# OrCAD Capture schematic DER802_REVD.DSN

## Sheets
1 PAGE1: size C; title: DER 802; rev: D
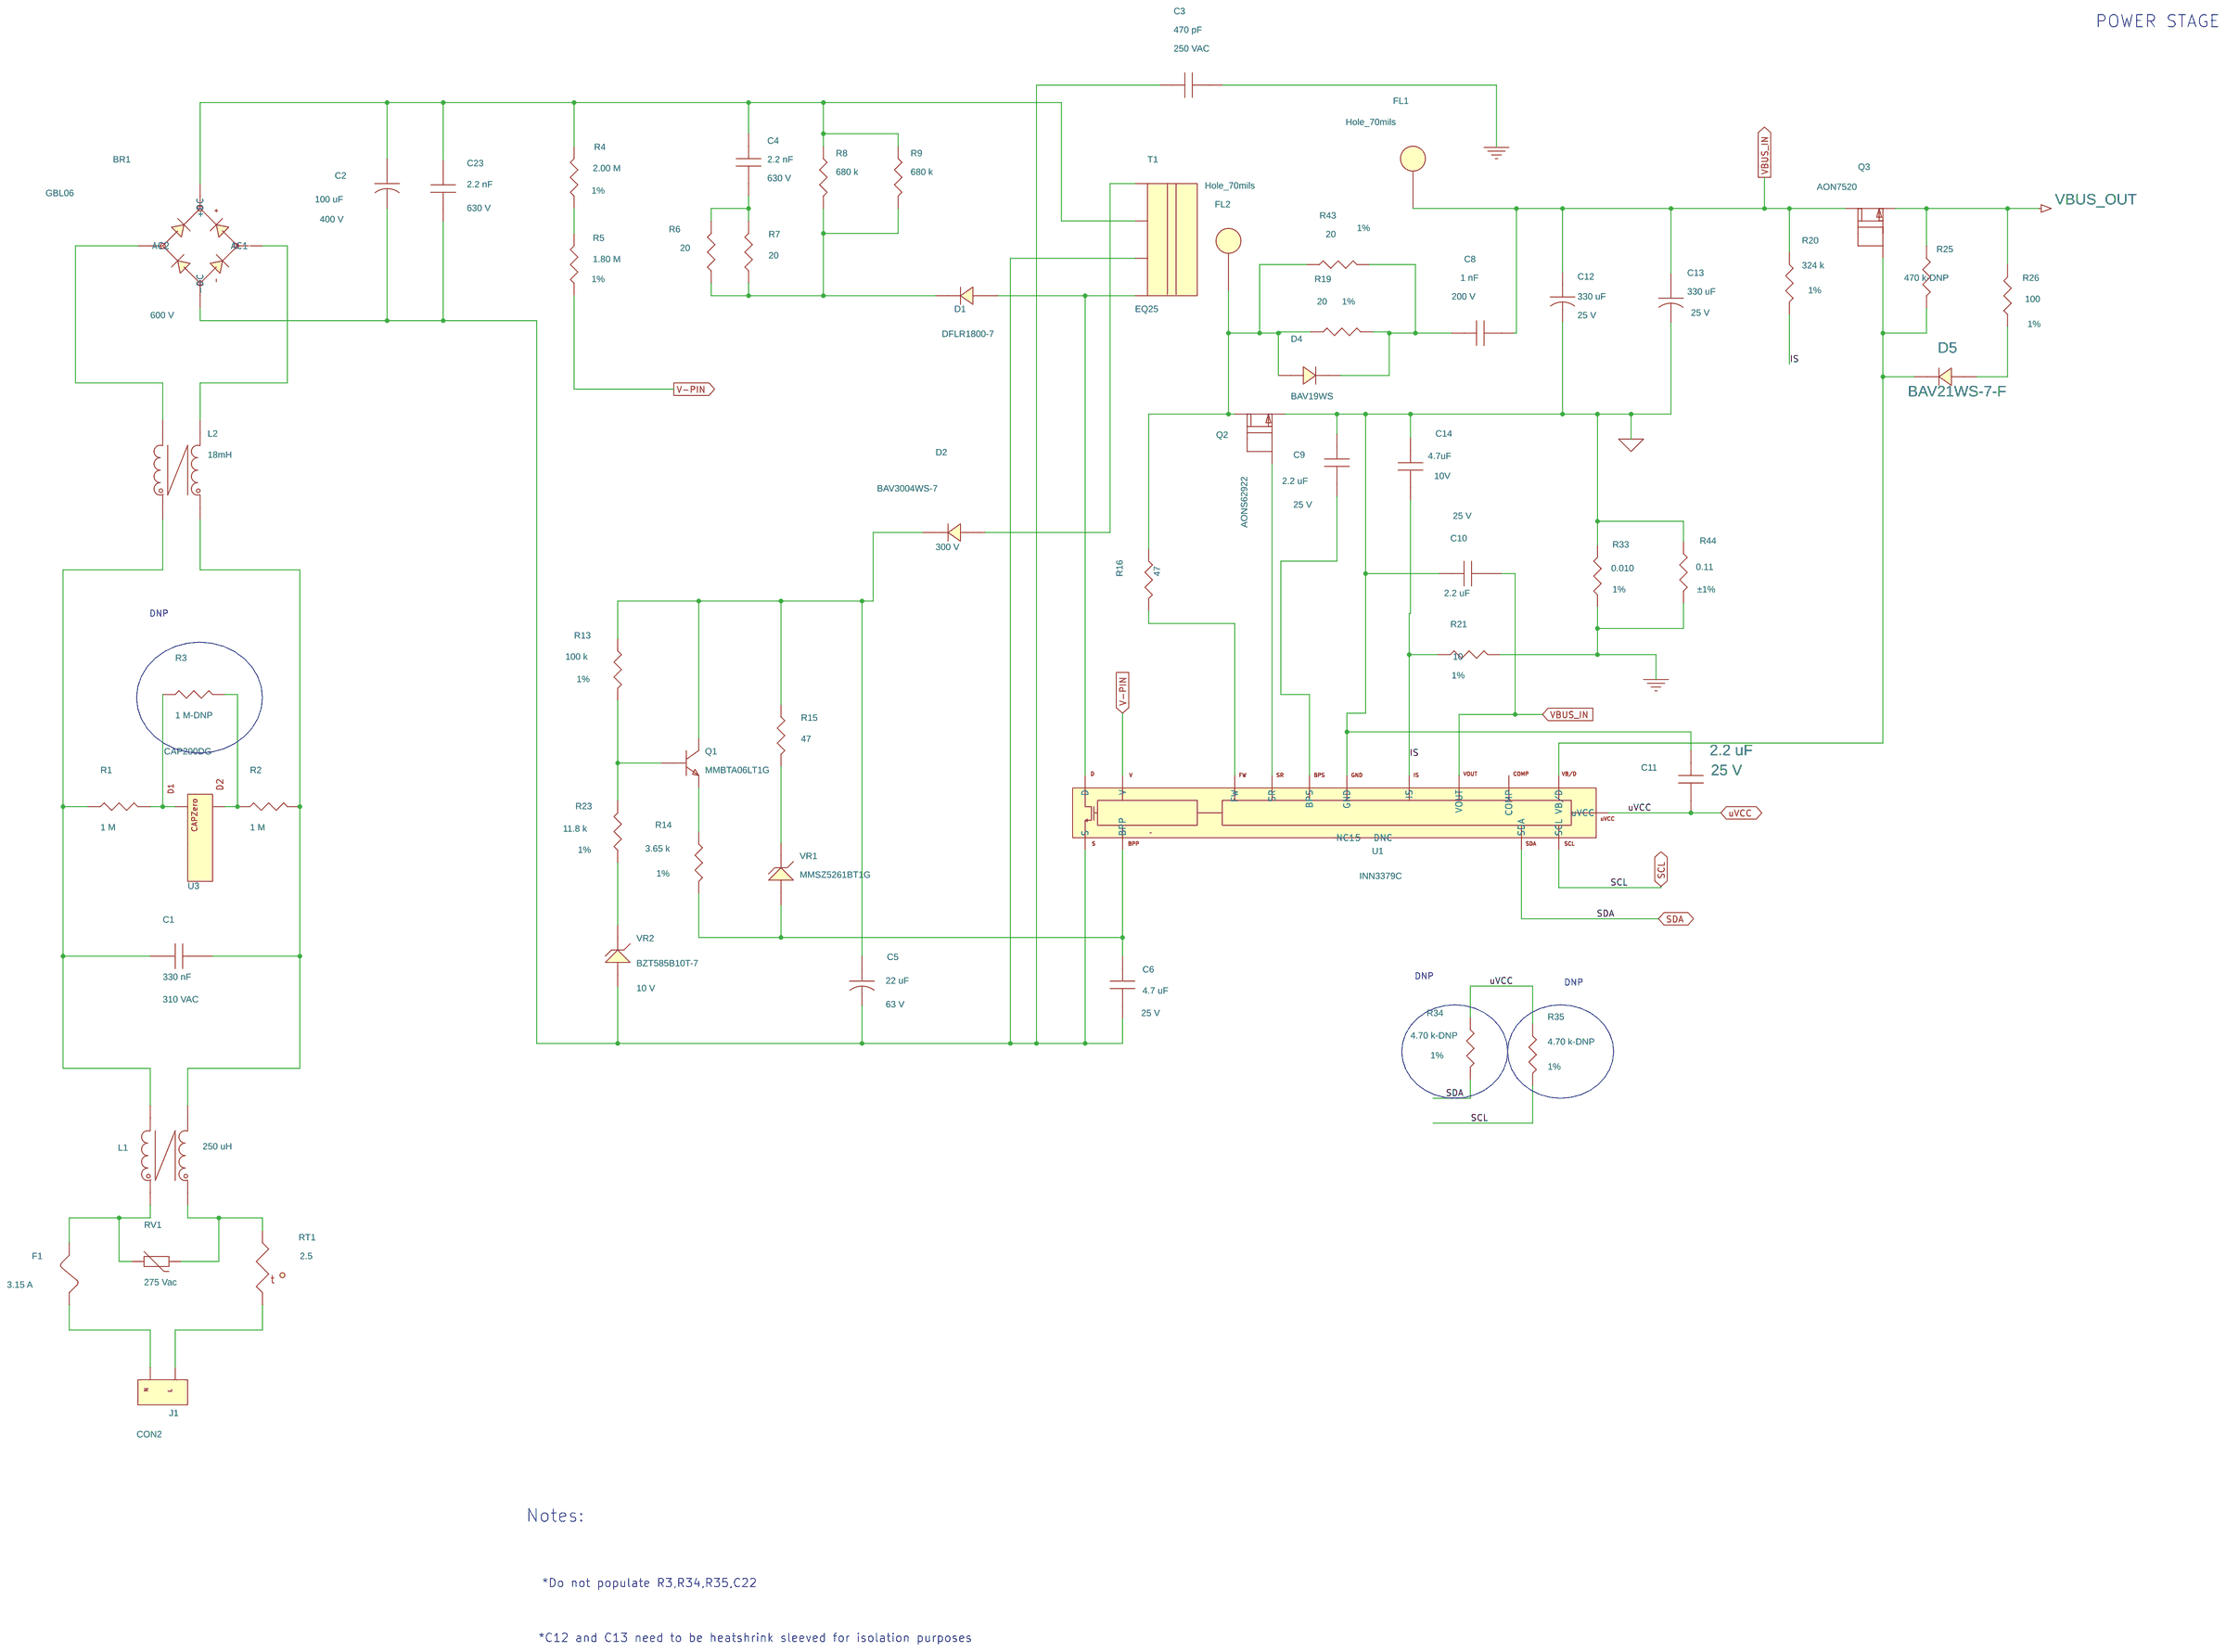
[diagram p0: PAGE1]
2 PAGE2: size Custom; rev: A
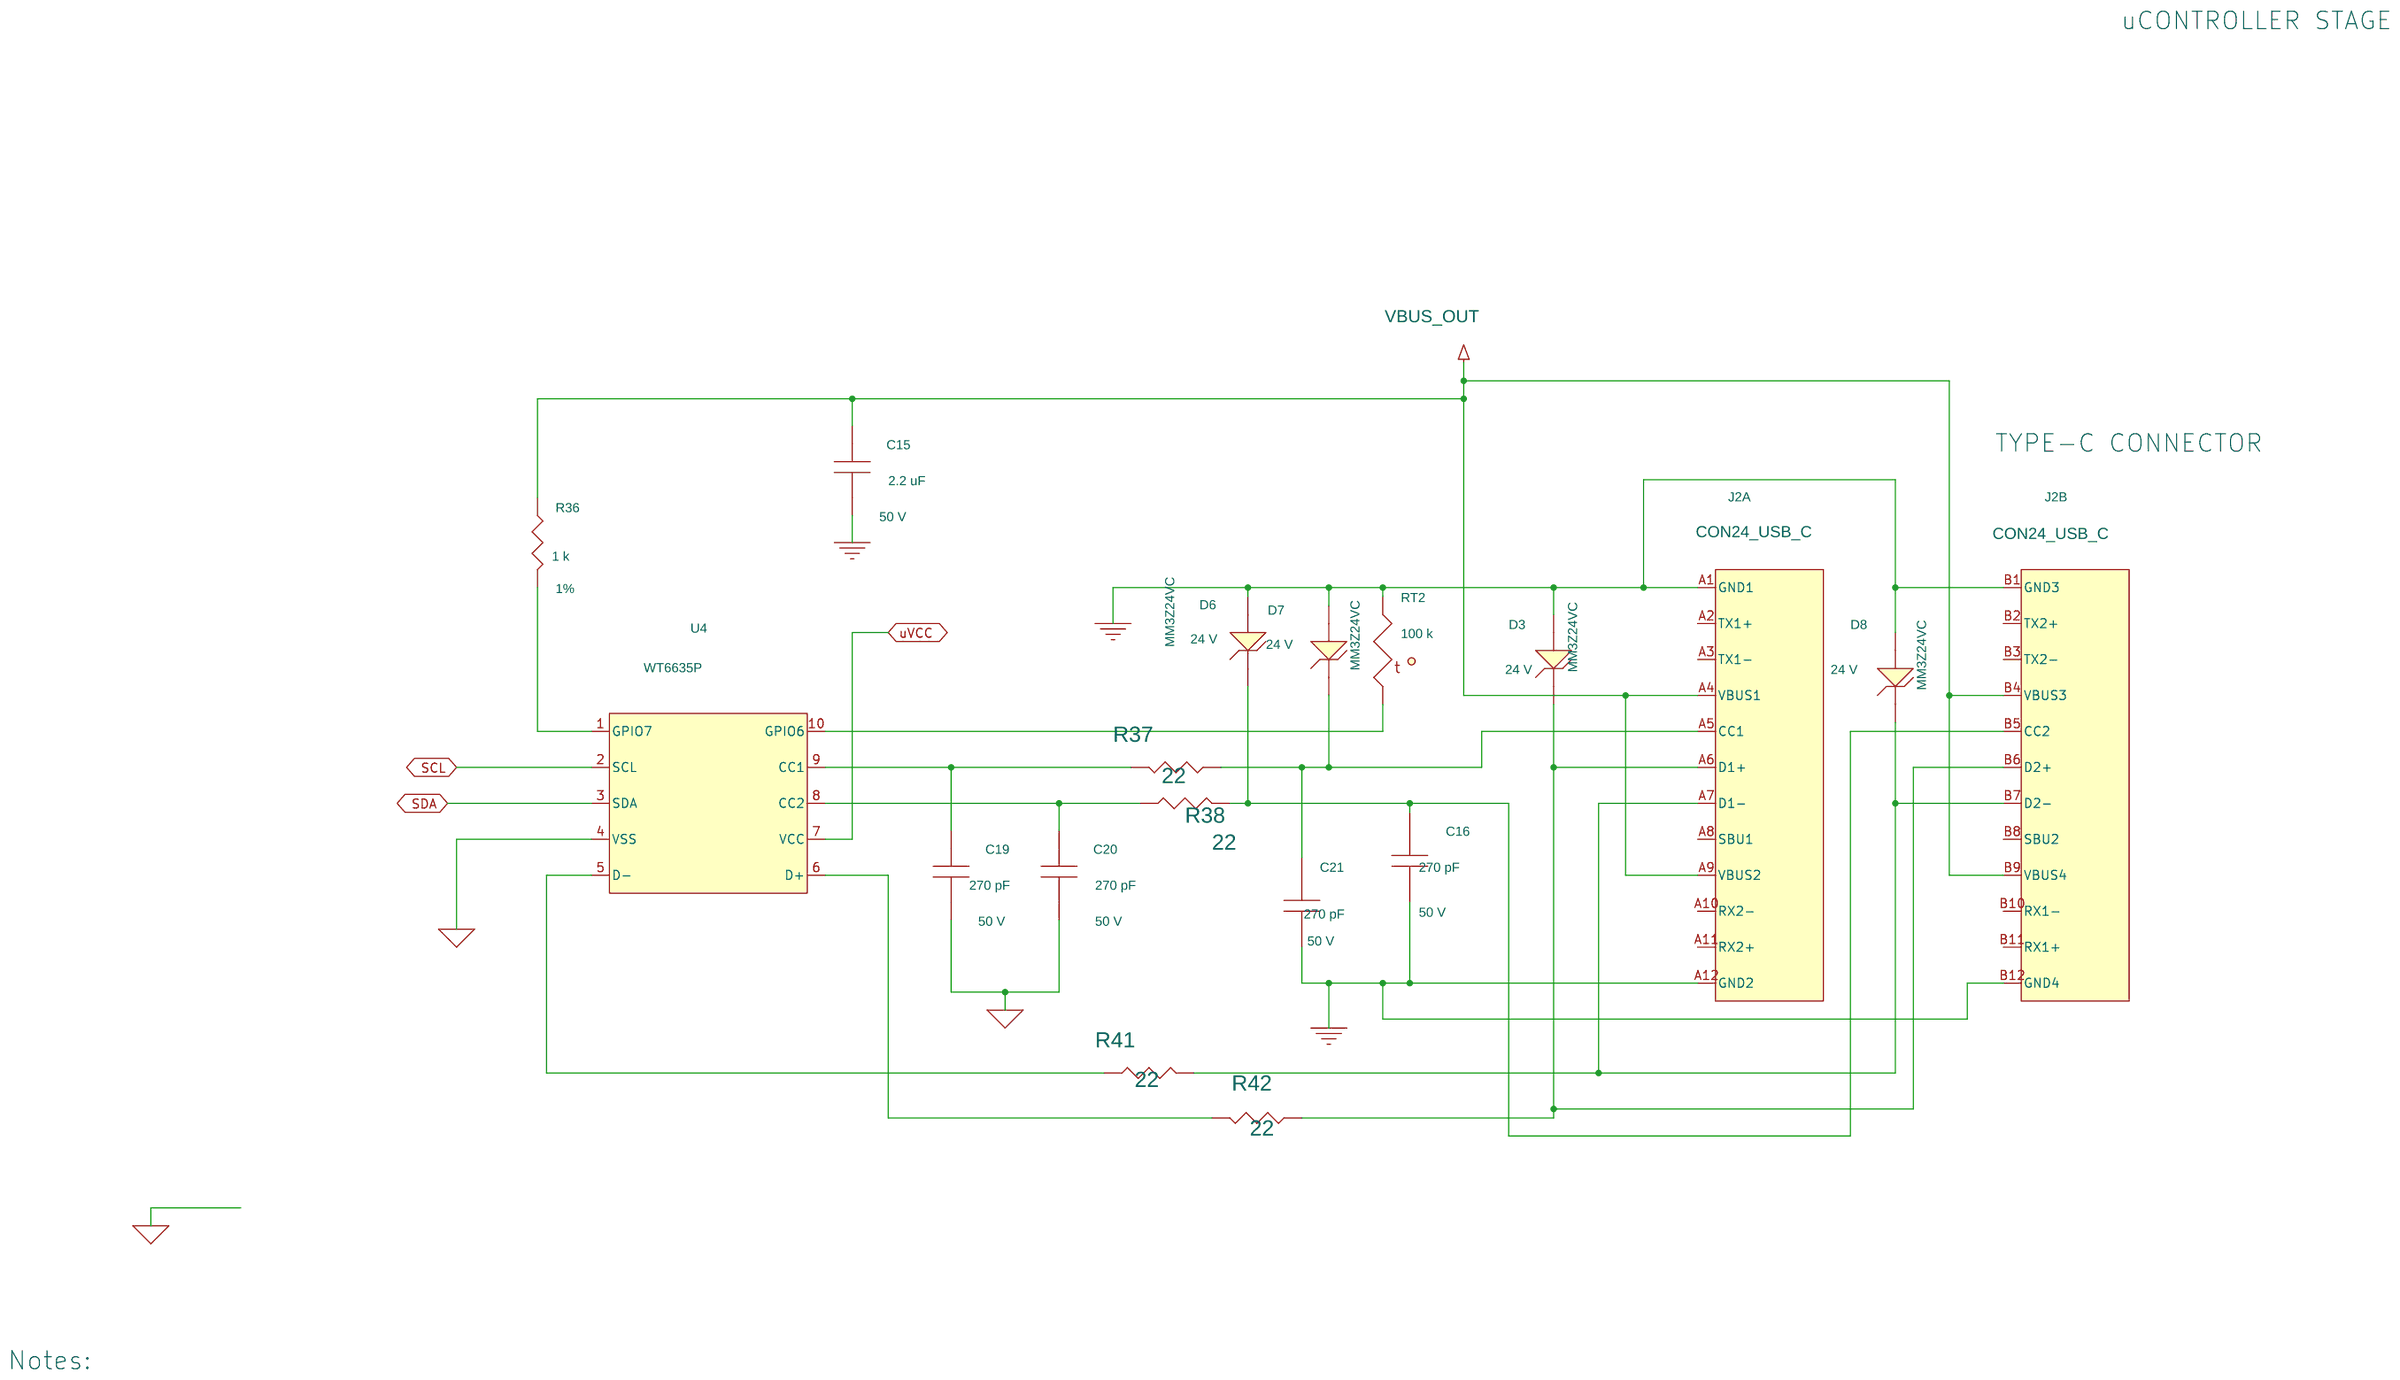
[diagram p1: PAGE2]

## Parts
sheet PAGE1
BR1  GBL06  [pidaxbridgegbl06]
C1  330 nF  [pinpxcaprad710x315590046]
C2  100 uF  [pipolcapclyd630ls300040]
C3  470 pF  [pinpcaprad374x275ls394d040]
C4  2.2 nF  [pismc1206]
C5  22 uF  [pipolcapclyd200ls80030]
C6  4.7 uF  [pismc0805]
C8  1 nF  [pismc0805]
C9  2.2 uF  [pismc0805]
C10  2.2 uF  [pismc0805]
C11  2.2 uF  [pismc0805]
C12  330 uF  [pipolcapcyld315ls138d030]
C13  330 uF  [pipolcapcyld315ls138d030]
C14  4.7uF  [pismc0603]
C23  2.2 nF  [pismc1206]
D1  DFLR1800-7  [pismddflr120012]
D2  BAV3004WS-7  [pismsod323]
D4  BAV19WS  [pismsod323]
D5  BAV21WS-7-F  [pismsod323]
F1  3.15 A  [pi_rst_microfuse]
FL1  Hole_70mils  [pi_hole_70mil]
FL2  Hole_70mils  [pi_hole_70mil]
J1  CON2  [PI_IEC320-C8]
L1  250 uH  [pi_toroid_CMC4p_V_275uH]
L2  18mH  [pi_CMC_18mH_Sumida]
Q1  MMBTA06LT1G  [pismsot23123_1]
Q2  AONS62922  [pismpqfn5x6b]
Q3  AON7520  [pism8dfn_ep3p3x3p3a]
R1  1 M  [pismr1206]
R2  1 M  [pismr1206]
R3  1 M-DNP  [pismr1206]
R4  2.00 M  [pismr1206]
R5  1.80 M  [pismr1206]
R6  20  [pismr1206]
R7  20  [pismr1206]
R8  680 k  [pismr1206]
R9  680 k  [pismr1206]
R13  100 k  [pismr0603]
R14  3.65 k  [pismr0603]
R15  47  [pismr0603]
R16  47  [pismr0603]
R19  20  [pismr1206]
R20  324 k  [pismr0805]
R21  10  [pismr0603]
R23  11.8 k  [pismr0805]
R25  470 k-DNP  [pismr0603]
R26  100  [pismr0603]
R33  0.010  [pismr0805]
R34  4.70 k-DNP  [pismr0402]
R35  4.70 k-DNP  [pismr0402]
R43  20  [pismr1206]
R44  0.11  [pismr0805]
RT1  2.5  [pi_rad150x300ls200d030]
RV1  275 Vac  [pidisc350x160ls210x140040]
T1  EQ25  [pi_bobbin_eq-2515p5_4p]
U1  INN3379C  [pi_ic_insop_24d]
U3  CAP200DG  [pi_ic_smd_so8_capzero]
VR1  MMSZ5261BT1G  [pi_sm_sod-123_12]
VR2  BZT585B10T-7  [pi_sm_d_ssmini2p]
sheet PAGE2
C15  2.2 uF  [pismc1206]
C16  270 pF  [pismc0603]
C19  270 pF  [pismc0603]
C20  270 pF  [pismc0603]
C21  270 pF  [pismc0603]
D3  MM3Z24VC  [pismsod323F]
D6  MM3Z24VC  [pismsod323F]
D7  MM3Z24VC  [pismsod323F]
D8  MM3Z24VC  [pismsod323F]
J2  CON24_USB_C  [pi_conn_USBC_Wurth]  (sections A,B)
R36  1 k  [pismr0603]
R37  22  [pismr0603]
R38  22  [pismr0603]
R41  22  [pismr0603]
R42  22  [pismr0603]
RT2  100 k  [pismr0603]
U4  WT6635P  [pismsop10]

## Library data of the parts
BR1 = DISCRETE_BRIDGE_+~~-: Disp_Voltage: 600 V; Part Number: 15-01112-00
C1 = CAP_NP: Disp_Voltage: 310 VAC; Part Number: 20-08604-00; Voltage: 310 VAC
C2 = CAP_POL: ALT_SYMBOLS: pipolcapclyd630ls3000401120h; COMPGROUP: 1; Disp_Voltage: 400 V; FPLIST: pipolcapclyd630ls300040,pipolcapclyd630ls3000401120h; Part Number: 20-00517-00; Voltage: 400 V
C3 = CAP_NP: COMPGROUP: 3; Disp_Voltage: 250 VAC; PCB Editor PCBFP: pinpycaprad540x290ls400040; Part Number: 20-09075-00; Voltage: 250 VAC
C4 = CAP_NP_0: Disp_Voltage: 630 V; Part Number: 20-08609-00; Voltage: 630 V
C5 = CAP_POL: ALT_SYMBOLS: pipolcapclyd5p0x12p5ls2p0d30h; Disp_Voltage: 63 V; FPLIST: pipolcapclyd200ls80030,pipolcapclyd5p0x12p5ls2p0d30h; Part Number: 20-09168-00; Voltage: 63 V
C6 = CAP_NP: Disp_Voltage: 25 V; Part Number: 20-09022-00; Voltage: 25 V
C8 = CAP_NP: ALT_SYMBOLS: pismc0805_1; Disp_Voltage: 200 V; FPLIST: pismc0805,pismc0805_1; PCB Editor PCBFP: pismc0603; Part Number: 20-00737-00; Voltage: 200 V
C9 = CAP_NP_0: Disp_Voltage: 25 V; Part Number: 20-08603-00; Voltage: 25 V
C10 C11 = CAP_NP: Disp_Voltage: 25 V; Part Number: 20-08603-00; Voltage: 25 V
C12 C13 = CAP_POL: ALT_SYMBOLS: pipolcapcyld315ls138d030h; Disp_Voltage: 25 V; FPLIST: pipolcapcyld315ls138d030,pipolcapcyld315ls138d030h; Part Number: 20-09107-00; Voltage: 25 V
C14 = CAP_NP: Disp_Voltage: 10V; Part Number: 20-08591-00; Voltage: 10 V
C23 = CAP_NP: Disp_Voltage: 630 V; Part Number: 20-08609-00; Voltage: 630 V
D1 = DIODE: COMPGROUP: 2; Part Number: 15-00919-00
D2 = DIODE: COMPGROUP: 1; Disp_Voltage: 300 V; Part Number: 15-01138-00
D4 = DIODE: Part Number: 15-00658-00
D5 = DIODE: COMPGROUP: 1; Part Number: 15-00385-00
F1 = FUSE: ALT_SYMBOLS: pirstmicrofusehoz; COMPGROUP: 1; FPLIST: pi_rst_microfuse,pirstmicrofusehoz; Part Number: 40-00020-00
FL1 FL2 = FlyingLead: Part Number: 35-00282-00
J1 = CON2_ACIN: Part Number: 35-00360-00
L1 = TORRID_4P_12_34: ALT_SYMBOLS: pi_toroid_CMC4p_V,pi_toroid_CMC4p_V_275uH; FPLIST: pi_toroid_CMC4p_H,pi_toroid_CMC4p_V,pi_toroid_CMC4p_V_275uH; Part Number: 32-00367-00
L2 = TORRID_4P_12_43a: Part Number: 30-00462-00
Q1 = NPN_BEC: Part Number: 55-00072-00
Q2 = FET_N_SGD_123_4_5678: Part Number: 50-00275-00
Q3 = FET_N_SGD_123_4_5678: Part Number: 50-00300-00
R1-R3 = R: Part Number: 05-01424-00
R4 = R: Disp_Tol: 1%; Part Number: 05-03156-00
R5 = R: Disp_Tol: 1%; Part Number: 05-03155-00
R6 R7 = R: Part Number: 05-01311-00
R8 R9 = R: Part Number: 05-01420-00
R13 = R: Disp_Tol: 1%; Part Number: 05-01174-00
R14 = R: Disp_Tol: 1%; Part Number: 05-01132-00
R15 R16 = R: Part Number: 05-01656-00
R19 R43 = R: Disp_Tol: 1%; Part Number: 05-00030-00
R20 = R: Disp_Tol: 1%; Part Number: 05-00829-00
R21 = R: Disp_Tol: 1%; Part Number: 05-00886-00
R23 = R: Disp_Tol: 1%; Part Number: 05-00691-00
R25 = R: Part Number: 05-01752-00
R26 = R: Disp_Tol: 1%; Part Number: 05-00982-00
R33 = R: Disp_Tol: 1%; Part Number: 05-06574-00
R34 R35 = R: ALT_SYMBOLS: RC0402; Disp_Tol: 1%; FPLIST: pismr0402,RC0402; Part Number: 05-05899-00
R44 = R: Disp_Tol: ±1%; Part Number: 05-06526-00
RT1 = THERMISTOR: ALT_SYMBOLS: pirad400x300ls200040_h; FPLIST: pi_rad150x300ls200d030,pirad400x300ls200040_h; Part Number: 90-00040-00
RV1 = VARISTOR: ALT_SYMBOLS: pi_disc_354x220_ls220x10_040_h; FPLIST: pidisc350x160ls210x140040,pi_disc_354x220_ls220x10_040_h; Part Number: 85-00015-00
T1 = BEQ2506_4P: Part Number: 25-01141-00
U1 = DEV_InnoPro: Part Number: 10-01092-00
U3 = CAPZero: Part Number: 10-00958-00
VR1 = DIODE_ZENER: Part Number: 15-01102-00
VR2 = DIODE_ZENER: Disp_Voltage: 10 V; Part Number: 15-01640-00
C15 = CAP_NP: Disp_Voltage: 50 V; Part Number: 20-09241-00; Voltage: 50 V
C16 C19-C21 = CAP_NP: Disp_Voltage: 50 V; Part Number: 20-09122-00; Voltage: 50 V
D3 D6-D8 = DIODE_ZENER: Disp_Voltage: 24 V; Part Number: 15-01590-00
J2 = CON24_USB: Part Number: 35-00414-00
R36 = R: Disp_Tol: 1%; Part Number: 05-01078-00
R37 R38 R41 R42 = R: COMPGROUP: 1; Part Number: 05-01648-00
RT2 = THERMISTOR: Part Number: 90-00078-00
U4 = WT6635P-10: Part Number: 45-00487-00

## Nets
GND: C3.2 C15.2 C16.1 C21.1 D3.2 D6.2 D7.2 D8.2 J2.A1(GND1) J2.A12(GND2) J2.B1(GND3) J2.B12(GND4) R21.2 R33.1 R44.2 RT2.1
GND_SIGNAL: C9.1 C10.1 C11.1 C12.2 C13.2 C14.1 C19.2 C20.2 Q2.1(S) R33.2 R44.1 U1.2(GND) U4.4(VSS)
VBUS_IN: C8.2 C10.2 C12.1 C13.1 FL1.1 Q3.5(D) R20.1 U1.10(VOUT)
VBUS_OUT: C15.1 J2.A4(VBUS1) J2.A9(VBUS2) J2.B4(VBUS3) J2.B9(VBUS4) Q3.1(S) R25.1 R26.2 R36.2
IS: C14.2 R20.2 R21.1 U1.1(IS)
SCL: R35.2 U1.5(SCL) U4.2(SCL)
SDA: R34.2 U1.6(SDA) U4.3(SDA)
uVCC: C11.2 R34.1 R35.1 U1.7(uVCC) U4.7(VCC)
V-PIN: R5.1 U1.13(V)
N10479111: F1.1 J1.1
N10805923: BR1.4(-DC) C2.2 C3.1 C5.2 C6.2 C23.2 T1.3 U1.16(S) VR2.2
N10806149: C6.1 R14.2 U1.14(BPP) VR1.2
N10813018: R4.1 R5.2
N10840366: BR1.1(+DC) C2.1 C4.1 C23.1 R4.2 R8.1 R9.1 T1.2
N10869805: C9.2 U1.4(BPS)
N10873526: R16.2 U1.11(FW)
N10873740: D4.2 FL2.1 Q2.5(D) R16.1 R19.2 R43.2
N10950053: C5.1 D2.1 Q1.3(COLLECTOR) R13.1 R15.1
N10950141: Q1.2(EMITTER) R14.1
N10950189: Q1.1(BASE) R13.2 R23.1
N10966650: D1.2 T1.4 U1.24(D)
N11036082: D1.1 R6.1 R7.1 R8.2 R9.2
N11077448: R15.2 VR1.1
N11090626: J1.2 RT1.2
N11099981: C1.1 L1.4 L2.4 R1.1
N11100013: C1.2 L1.2 L2.1 R2.2
N11100021: BR1.3(AC2) L2.3
N11100037: BR1.2(AC1) L2.2
N11100069: R1.2 R3.1 U3.2(D1)
N11105883: D2.2 T1.1
N11108210: F1.2 L1.3 RV1.1
N11139619: C4.2 R6.2 R7.2
N11156493: C8.1 D4.1 R19.1 R43.1
N11376604: L1.1 RT1.1 RV1.2
N11381167: R2.1 R3.2 U3.7(D2)
N11471224: D5.1 Q3.4(G) R25.2 U1.8(VB/D)
N12152275: D5.2 R26.1
N12152539: Q2.4(G) U1.9(SR)
N12163734: R36.1 U4.1(GPIO7)
N12163888: C16.2 D6.1 J2.B5(CC2) R38.1
N12163892: C21.2 D7.1 J2.A5(CC1) R37.2
N12163896: RT2.2 U4.10(GPIO6)
N12163904: D3.1 J2.A6(D1+) J2.B6(D2+) R42.2
N12163956: D8.1 J2.A7(D1-) J2.B7(D2-) R41.1
N12164018: C19.1 R37.1 U4.9(CC1)
N12164084: C20.1 R38.2 U4.8(CC2)
N12164230: R41.2 U4.5(D-)
N12164238: R42.1 U4.6(D+)
N12168266: R23.2 VR2.1

Not connected (* = marked no-connect by the designer): J2 A2(TX1+) A3(TX1-) A8(SBU1) A10(RX2-) A11(RX2+) B2(TX2+) B3(TX2-) B8(SBU2) B10(RX1-) B11(RX1+); Q2 2(S2) 3(S3) 6(D6) 7(D7) 8(D8); Q3 2(S2) 3(S3) 6(D6) 7(D7) 8(D8); U1 3(COMP) 12(DNC) 15(NC15); U3 1(NC1) 3(NC2) 4(NC3) 5(NC4) 6(NC5) 8(NC8)

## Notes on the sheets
sheet 1
- POWER STAGE
- DNP
- DNP
- DNP
- Notes:
- *Do not populate R3,R34,R35,C22
- *C12 and C13 need to be heatshrink sleeved for isolation purposes
sheet 2
- uCONTROLLER STAGE
- TYPE-C CONNECTOR
- Notes:
